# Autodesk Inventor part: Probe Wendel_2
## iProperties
Created: 2009-08
Part Number: Probe Wendel_2
Document SubType Name: Modeling
Designer: dreamlab
Density: 1 g/cm^3
Author: dreamlab
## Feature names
1. Coil1
2. Rectangular Pattern6
